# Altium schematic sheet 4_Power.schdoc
size 431 x 309 mm
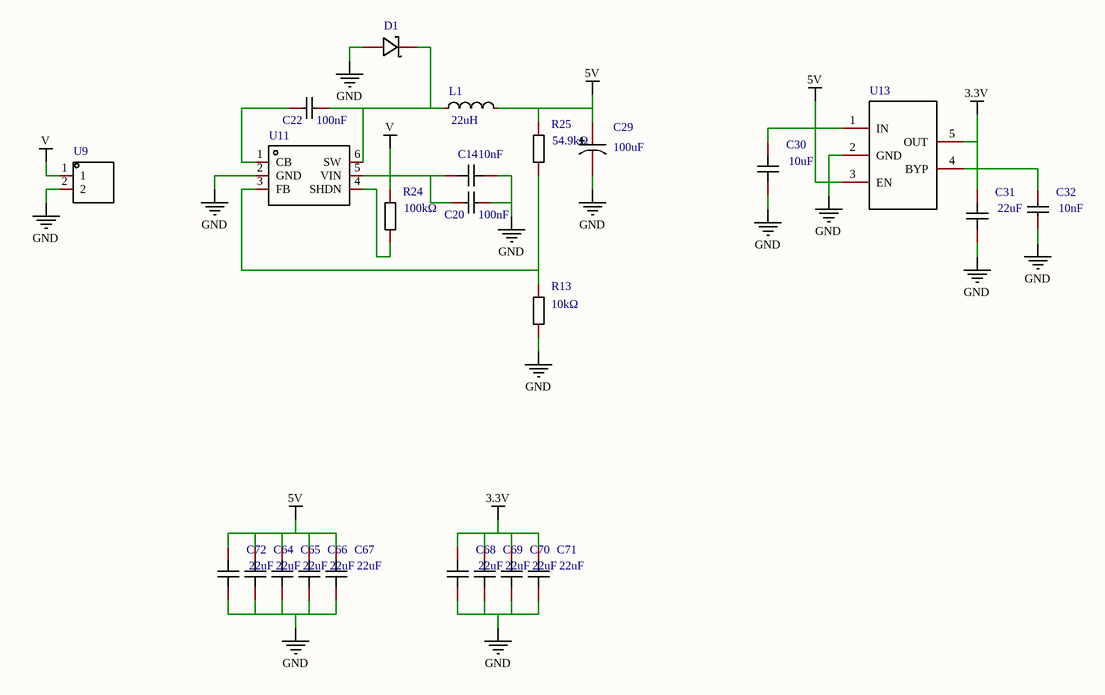
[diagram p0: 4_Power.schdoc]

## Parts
C14  value 10nF  [C0402]  (hidden comment: CC0402KRX7R0BB103)
C20  value 100nF  [C0805]  (hidden comment: CL21B104KCFNNNE)
C22  value 100nF  [C0805]  (hidden comment: CL21B104KCFNNNE)
C29  value 100uF  [CAP-SMD_L3.2-W1.6]  (hidden comment: TLJA107M010R1400)
C30  value 10uF  [C0402]  (hidden comment: CL05A106MP5NUNC)
C31  value 22uF  [C0402]  (hidden comment: GRM155R60J226ME11D)
C32  value 10nF  [C0402]  (hidden comment: CL05B103KB5NNNC)
C64  value 22uF  [C0603]  (hidden comment: CL10A226MP8NUNE)
C65  value 22uF  [C0603]  (hidden comment: CL10A226MP8NUNE)
C66  value 22uF  [C0603]  (hidden comment: CL10A226MP8NUNE)
C67  value 22uF  [C0603]  (hidden comment: CL10A226MP8NUNE)
C68  value 22uF  [C0603]  (hidden comment: CL10A226MP8NUNE)
C69  value 22uF  [C0603]  (hidden comment: CL10A226MP8NUNE)
C70  value 22uF  [C0603]  (hidden comment: CL10A226MP8NUNE)
C71  value 22uF  [C0603]  (hidden comment: CL10A226MP8NUNE)
C72  value 22uF  [C0603]  (hidden comment: CL10A226MP8NUNE)
D1  DSK16  [SOD-123_L2.8-W1.8-LS3.7-RD]  (value not drawn)
L1  value 22uH  [L1210]  (hidden comment: CBC3225T220KR)
R13  value 10kΩ  [R0402]  (hidden comment: 0402WGF1002TCE)
R24  value 100kΩ  [R0402]  (hidden comment: PTFR0402B100KN9)
R25  value 54.9kΩ  [R0402]  (hidden comment: RTT025492FTH)
U9  436500215  [CONN-TH_436500215]  (value not drawn)
U11  LMR16006XDDCR  [SOT-23-6_L2.9-W1.6-P0.95-LS2.8-BR]  (value not drawn)
U13  SPX3819M5-L-3-3/TR  [SOT-23-5_L3.0-W1.7-P0.95-LS2.8-BR]  (value not drawn)

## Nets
3.3V: C31.2 C68.2 C69.2 C70.2 C71.2 U13.5(OUT)
5V: C29.1 C30.2 C64.2 C65.2 C66.2 C67.2 C72.2 L1.2 R25.2 U13.1(IN) U13.3(EN)
GND: C14.2 C20.2 C29.2 C30.1 C31.1 C32.1 C64.1 C65.1 C66.1 C67.1 C68.1 C69.1 C70.1 C71.1 C72.1 D1.2(A) R13.1 U9.2 U11.2(GND) U13.2(GND)
V: C14.1 C20.1 R24.2 U9.1 U11.5(VIN)
NetC22_1: C22.1 U11.1(CB)
NetC22_2: C22.2 D1.1(K) L1.1 U11.6(SW)
NetC32_2: C32.2 U13.4(BYP)
NetR13_2: R13.2 R25.1 U11.3(FB)
NetR24_1: R24.1 U11.4(SHDN)

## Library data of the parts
C14 = CC0402KRX7R0BB103: Capacitance:10nF Tolerance:±10% Tolerance:±10% Voltage Rated:100V Temperature Coefficient:X7R; Manufacturer: YAGEO(国巨); Add into BOM: yes; Tolerance: ±10%; Voltage Rated: 100V; Temperature Coefficient: X7R
C20 C22 = CL21B104KCFNNNE: Capacitance:100nF Tolerance:±10% Tolerance:±10% Voltage Rated:100V Temperature Coefficient:X7R; Manufacturer: SAMSUNG(三星); Add into BOM: yes; Tolerance: ±10%; Voltage Rated: 100V; Temperature Coefficient: X7R
C29 = TLJA107M010R1400: Capacitance:100uF Tolerance:±20% Tolerance:±20% Rated Voltage:10V Equivalent Series Resistance(ESR):1.4Ω@100kHz Operating Temperature:-55~+125 Operating Temperature:-55~+125; Manufacturer: AVX; Add into BOM: yes; Tolerance: ±20%; Rated Voltage: 10V
C30 = CL05A106MP5NUNC: Capacitance:10uF Tolerance:±20% Tolerance:±20% Voltage Rated:10V Temperature Coefficient:X5R; Manufacturer: SAMSUNG(三星); Symbol: CL05A106MP5NUNC_C315248; Add into BOM: yes; Tolerance: ±20%; Voltage Rated: 10V; Temperature Coefficient: X5R
C31 = GRM155R60J226ME11D: Capacitance:22uF Tolerance:±20% Tolerance:±20% Voltage Rated:6.3V Temperature Coefficient:X5R; Manufacturer: muRata(村田); Add into BOM: yes; Tolerance: ±20%; Voltage Rated: 6.3V; Temperature Coefficient: X5R
C32 = CL05B103KB5NNNC: Capacitance:10nF Tolerance:±10% Tolerance:±10% Voltage Rated:50V Temperature Coefficient:X7R; Manufacturer: SAMSUNG(三星); Add into BOM: yes; Tolerance: ±10%; Voltage Rated: 50V; Temperature Coefficient: X7R
C64-C72 = CL10A226MP8NUNE: Temperature Coefficient:X5R Tolerance:±20% Tolerance:±20% Voltage Rated:10V Capacitance:22uF; Manufacturer: SAMSUNG(三星); Add into BOM: yes; Temperature Coefficient: X5R; Tolerance: ±20%; Voltage Rated: 10V
D1 = DSK16: Reverse Voltage (Vr):60V Average Rectified Current (Io):1A Forward Voltage (Vf@If):700mV@1A; Manufacturer: MDD; Add into BOM: yes; Reverse Voltage (Vr): 60V; Average Rectified Current (Io): 1A
L1 = CBC3225T220KR: Inductance:22uH Tolerance:±10% Tolerance:±10% Rated Current:620mA Saturation Current (Isat):- DC Resistance (DCR):270mΩ Q @ Freq:- Frequency - Self Resonant:- Ratings:-; Manufacturer: TAIYO YUDEN(太诱); Add into BOM: yes; Tolerance: ±10%; Rated Current: 620mA; DC Resistance (DCR): 270mΩ
R13 = 0402WGF1002TCE: Type:厚膜电阻 Resistance:10kΩ Tolerance:±1% Tolerance:±1% Power(Watts):1/16W Temperature Coefficient:±100ppm/ Temperature Coefficient:±100ppm/ Overload Voltage (Max):50V Operating Temperature Range:-55~+155 Operating Temperature Range:-55~+155; Manufacturer: UNI-ROYAL(厚声); Add into BOM: yes; Tolerance: ±1%; Power(Watts): 1/16W; Overload Voltage (Max): 50V
R24 = PTFR0402B100KN9: Type:薄膜电阻 Resistance:100kΩ Tolerance:±0.1% Power(Watts):60mW Temperature Coefficient:±10ppm/ Temperature Coefficient:±10ppm/ Overload Voltage (Max):75V Operating Temperature Range:-55~+125 Operating Temperature Range:-55~+125; Manufacturer: RESI(开步睿思）; Add into BOM: yes; Tolerance: ±0.1%; Power(Watts): 60mW; Temperature Coefficient: ±10ppm/; Overload Voltage (Max): 75V
R25 = RTT025492FTH: Type:厚膜电阻 Resistance:54.9kΩ Tolerance:±1% Power(Watts):1/16W Temperature Coefficient:±100ppm/ Temperature Coefficient:±100ppm/ Overload Voltage (Max):50V Operating Temperature Range:-55~+155 Operating Temperature Range:-55~+155; Manufacturer: RALEC(旺诠); Add into BOM: yes; Tolerance: ±1%; Power(Watts): 1/16W; Overload Voltage (Max): 50V
U9 = 436500215: Reference Series:- Pitch:3mm Pins Structure:1x2P Number of Rows:1 Number of PINs Per Row:2 Row Spacing:- Mounting Style:- Contact Material:黄铜; Manufacturer: MOLEX; Add into BOM: yes; Pitch: 3mm; Pins Structure: 1x2P; Number of PINs Per Row: 2
U11 = LMR16006XDDCR: Manufacturer: TI(德州仪器); Add into BOM: yes
U13 = SPX3819M5-L-3-3/TR: Output Type:固定 Output Polarity:正 Number of Outputs:1 Maximum Input Voltage:16V Output Voltage:3.3V Output Voltage:3.3V Dropout Voltage:700mV@(500mA) Output Current:500mA Power Supply Rejection Ratio (PRSS):70dB; Manufacturer: MaxLinear; Add into BOM: yes; Output Type: 固定; Output Polarity: 正; Number of Outputs: 1; Maximum Input Voltage: 16V; Output Voltage: 3.3V; Power Supply Rejection Ratio (PRSS): 70dB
